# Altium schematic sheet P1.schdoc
size 210 x 149 mm; Symbol: Sheet-Symbol_A4; Company: 嘉立创EDA; Version: V1.0; Page Size: A4; @Project Name: L298N电机驱动模块; @Page Count: 1; @Update Date: 2023-05-31; @Create Date: 2023-05-31; @Schematic Name: Schematic1; @Page No: 1; @Page Name: P1; Device: Sheet-Symbol_A4
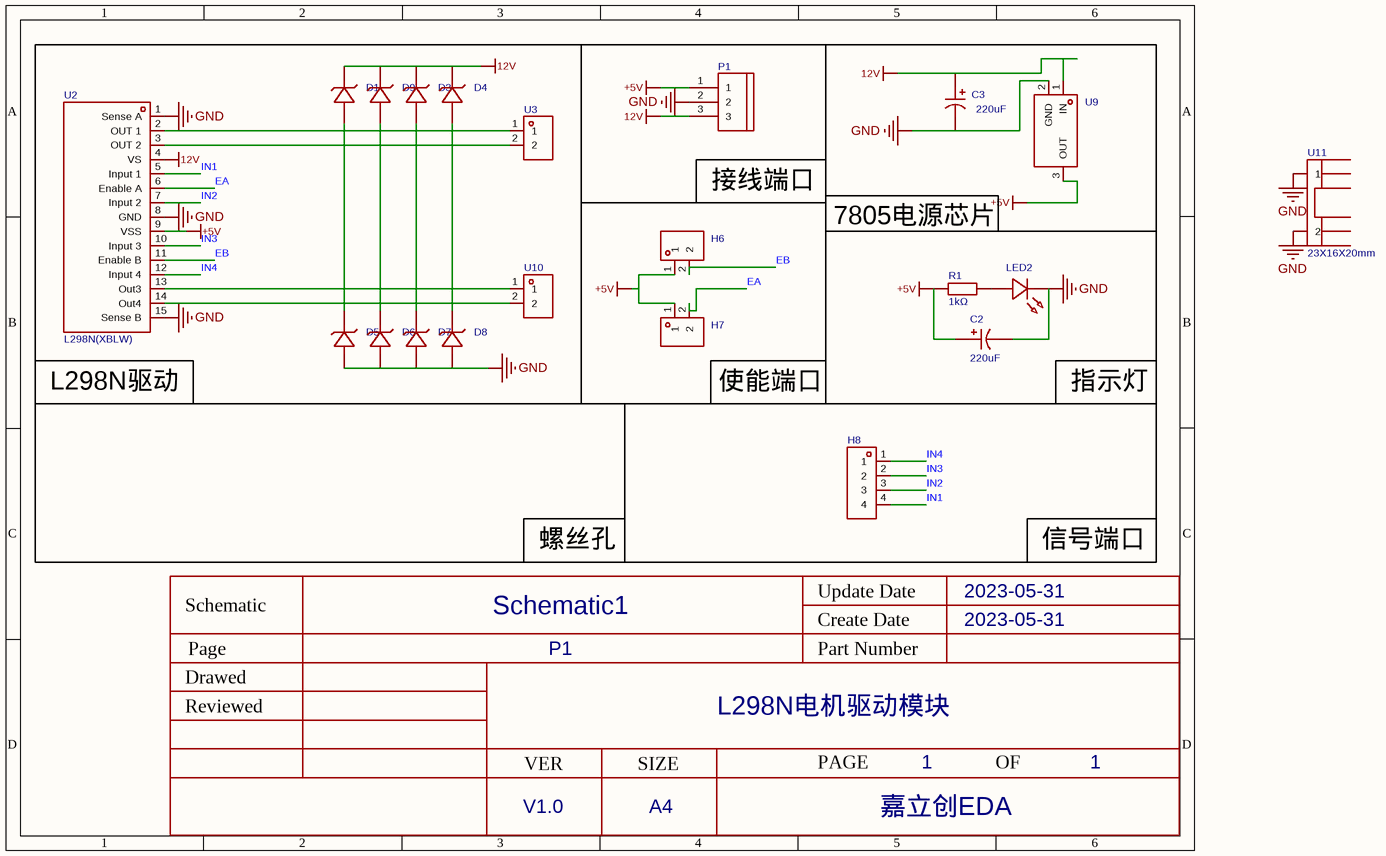
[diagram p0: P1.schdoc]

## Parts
C2  value 220uF  [CAP-SMD_BD8.0-L8.3-W8.3-LS9.3-FD]
C3  value 220uF  [CAP-SMD_BD8.0-L8.3-W8.3-LS9.3-FD]
D1  1N4007 A7  [SOD-123FL_L2.7-W1.8-LS3.8-RD]  (value not drawn)
D3  1N4007 A7  [SOD-123FL_L2.7-W1.8-LS3.8-RD]  (value not drawn)
D4  1N4007 A7  [SOD-123FL_L2.7-W1.8-LS3.8-RD]  (value not drawn)
D5  1N4007 A7  [SOD-123FL_L2.7-W1.8-LS3.8-RD]  (value not drawn)
D6  1N4007 A7  [SOD-123FL_L2.7-W1.8-LS3.8-RD]  (value not drawn)
D7  1N4007 A7  [SOD-123FL_L2.7-W1.8-LS3.8-RD]  (value not drawn)
D8  1N4007 A7  [SOD-123FL_L2.7-W1.8-LS3.8-RD]  (value not drawn)
D9  1N4007 A7  [SOD-123FL_L2.7-W1.8-LS3.8-RD]  (value not drawn)
H6  2541WV-02P  [HDR-TH_2P-P2.54-V-M-1]  (value not drawn)
H7  2541WV-02P  [HDR-TH_2P-P2.54-V-M-1]  (value not drawn)
H8  PZ2.54-1x4PZZ-L11.5  [HDR-TH_PZ2.54-1X4PZZ-L11.5]  (value not drawn)
LED2  GL0805UR01  [LED0805-R-RD_RED]  (value not drawn)
P1  (no value)  [CONN-TH_3P-P5.00_WJ500V-5.08-3P]
R1  value 1kΩ  [R0805]
U2  L298N(XBLW)  [MULTIWATT-15_L19.6-W5.0-P1.27-L]
U3  (no value)  [CONN-TH_DB302-5.0-2P]
U9  L78M05DTR(XBLW)  [TO-252-2_L6.6-W6.1-P4.60-LS10.0-BR-CW]  (value not drawn)
U10  (no value)  [CONN-TH_DB302-5.0-2P]
U11  23X16X20mm  [TH-2P_L23.5-W16.8]

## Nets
12V: C3.1 D1.1(K) D3.1(K) D4.1(K) D9.1(K) P1.3 U2.4(VS) U9.1(IN)
+5V: C2.1 H6.1 H7.1 P1.1 R1.2 U2.9(VSS) U9.3(OUT)
GND: C2.2 C3.2 D5.2(A) D6.2(A) D7.2(A) D8.2(A) LED2.2(C) P1.2 U2.1(Sense_A) U2.8(GND) U2.15(Sense_B) U9.2(GND) U11.1 U11.2
EA: H7.2 U2.6(Enable_A)
EB: H6.2 U2.11(Enable_B)
IN1: H8.4 U2.5(Input_1)
IN2: H8.3 U2.7(Input_2)
IN3: H8.2 U2.10(Input_3)
IN4: H8.1 U2.12(Input_4)
NetD1_2: D1.2(A) D5.1(K) U2.2(OUT_1) U3.1
NetD3_2: D3.2(A) D7.1(K) U2.13(Out3) U10.1
NetD4_2: D4.2(A) D8.1(K) U2.14(Out4) U10.2
NetD6_1: D6.1(K) D9.2(A) U2.3(OUT_2) U3.2
NetLED2_1: LED2.1(A) R1.1

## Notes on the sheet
- 接线端口
- 7805电源芯片
- (near U2) L298N驱动
- 使能端口
- 指示灯
- 螺丝孔
- 信号端口

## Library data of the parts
C2 C3 = EMK1VM221FB0D00R: 容值:220uF;精度:±20%;额定电压:35V;电容体直径:-;电容体长度:-;纹波电流:-;等效串联电阻:-;工作寿命:-;工作温度:-;; Manufacturer: AISHI(艾华集团); AddInBom: yes; ModelId: ae37c166a99f49b1b935231edf05d58d; ModelTransform: 366.1,326.8,0,0,0,0,0,0,0; Tolerance: ±20%; Rated Voltage: 35V
D1 D3-D9 = 1N4007 A7_C727082: 二极管配置:独立式;正向压降(Vf):1.1V@1A;直流反向耐压(Vr):1kV;整流电流:1A;; Manufacturer: TWGMC(迪嘉); Symbol: 1N4007_C727082; Add into BOM: yes; 3D Model: 86f9151e155e4fe2af0c4f2e0a80302e; 3D Model Transform: 141.732,70.866,0,180,0,0,0,0,0; Diode Configuration: 独立式; Voltage - DC Reverse(Vr): 1kV; Current - Rectified: 1A; Reverse Leakage Current (Ir): 5uA; Non-Repetitive Peak Forward Surge Current: 25A; Operating Junction Temperature Range: -55℃~+125℃; ModelName: SOD-123FL_L2.8-W1.8-H1.1-LS3.6
H6 H7 = 2541WV-02P: 插针结构:1x2P;间距:2.54mm;行距:-;圆针/方针:方针;安装方式:直插;排数:单排;总PIN位数:2P;额定电流:3A;配合针长度:6mm;塑高:2.54mm;端接针长度:3mm;触头材质:黄铜;触头镀层:金;工作温度:-55℃~+105℃;; Manufacturer: HanElectricity(瀚源); Add into BOM: yes; 3D Model: 79b2e9f2d70a4d68a1b7098f27c6d4c5; 3D Model Transform: 200,100,0,0,0,0,0,0,-118.11; Pitch: 2.54mm; Pin Structure: 1x2P; Circluar Pins/Square Pins: 方针; Current Rating: 3A; ModelName: HDR-M-2.54_1x2
H8 = PZ2.54-1x4PZZ-L11.5: 插针结构:1x4P;间距:2.54mm;行距:2.54mm;圆针/方针:方针;安装方式:直插;排数:单排;总PIN位数:4P;额定电流:3A;额定电压:250V;配合针长度:6mm;塑高:2.5mm;端接针长度:3mm;触头材质:黄铜;触头镀层:金;工作温度:-40℃~+105℃;颜色:黑色;; Manufacturer: SHOU HAN(首韩); Add into BOM: yes; Pitch: 2.54mm; Pin Structure: 1x4P; Circluar Pins/Square Pins: 方针; Voltage Rating (Max): 250V; Current Rating: 3A
LED2 = GL0805UR01: 灯头类型:2mmx1.25mm方形灯头;发光颜色:红色;正向压降(Vf):2.1V;功率:-;正向电流:20mA;波长:618nm~624nm;二极管配置:独立二极管;透镜颜色:无色透明透镜;色温:-;发光强度:100mcd;发光角度:120°;载带方式:正贴;工作温度:-40℃~+85℃;; Manufacturer: Guiguang light(桂光光电); Add into BOM: yes; 3D Model: f010e90d36544999ab4e363fdba5b490; 3D Model Transform: 78.74,49.21644,0,0,0,0,0,0,0; Diode Configuration: 独立二极管; Lens Color: 无色透明透镜; Forward Current: 20mA; Luminous Intensity: 100mcd; Viewing Angle: 120°; Illumination Color: 红色; Voltage - Forward(Vf): 2.1V
P1 = WJ500V-5.08-3P: 间距:5.08mm;排数:1;每排PIN数:3;安装方式:直针;额定电流:18A;额定电压:250V;线规 - AWG:14~30;线规 - mm?:2.5;工作温度范围:-40~+105;颜色:绿色;; Manufacturer: KANGNEX(康奈克斯电气); Symbol: WJ500V-5.08-3P-14-00A; AddInBom: yes; ModelId: f80d5090781743d49abcb05979f5618f; ModelName: CONN-TH_3P_L15.3-W10.2-P5.08; ModelTransform: 619.7,413.4,0,180,0,0,7.9,0,-157.5; Pitch: 5.08mm; Number of PINs Per Row: 3; Current Rating (Max): 18A; Voltage Rating (Max): 250V; Wire Gauge - AWG: 14~30; Wire Gauge - mm?: 2.5
R1 = RS-05K102JT: 阻值:1kΩ;精度:±5%;功率:125mW;温度系数:±100ppm/;最大工作电压:150V;工作温度范围:-55~+155;; Manufacturer: FH(风华); AddInBom: yes; ModelId: 37a81e68749a4138bd2dfa6897b24b85; ModelName: R0805_L2.0-W1.3-H0.6; ModelTransform: 78.74,51.181,0,0,0,0,0,-0.0005,0; Tolerance: ±5%; Power(Watts): 125mW; Overload Voltage (Max): 150V
U2 = L298N(XBLW): 马达驱动  双路全桥驱动，静态电流Iq(Typ)10mA，驱动电流 Iout4A; Manufacturer: XBLW(芯伯乐); Symbol: L298N (LX); Add into BOM: yes; 3D Model: 17dbda3c803a45a0ac2c74e6ab5d5790; 3D Model Transform: 787.7937,378.3457,0,0,0,0,0,78.74,-137.795; Control Voltage: 4.5V~46V; Output Current: 4A; Number of H-bridges: 2; Drive Type: 双极驱动; ModelName: SIP-15_L20.0-W4.6-P1.27-L
U3 U10 = DB302-5.0-2P-GN-S: Manufacturer: DIBO(地博电气); AddInBom: yes; ModelId: af2d1fe21b58404e908b9acd6fb20001; ModelTransform: 427.9519,354.33,0,0,0,0,16.727,0.827,-157.48
U9 = L78M05DTR(XBLW): 输出类型:固定;工作电压:36V;输出电压:5V;输出电流:500mA;电源纹波抑制比(PSRR):80dB@(120Hz);输出极性:正极;; Manufacturer: XBLW(芯伯乐); Add into BOM: yes; 3D Model: 2bfbfbb77002446c96d8a76a432e0188; 3D Model Transform: 246.80147,383.8575,0,90,0,0,-31.302,0.003,0; Output Type: 固定; Voltage - Supply: 36V; Output Voltage: 5V; Output Current: 500mA; Voltage Dropout: 2V@(500mA); standby current: 4mA; Output Configuration: 正极; Number of Outputs: 1
U11 = 23X16X20mm: 产品尺寸:23X16X20MM;材 质:6063-T5铝;; Manufacturer: XSD(鑫顺达); AddInBom: yes; ModelId: 2cbefff9b1144752bff89e4ca7508b190819f05c4eef4c71ace90d822a990e87; ModelTransform: 925.195,625.983,0,0,0,0,0,-59.055,-137.795; SurfaceTreatment: 本色洗白; NumberOfNails: 2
